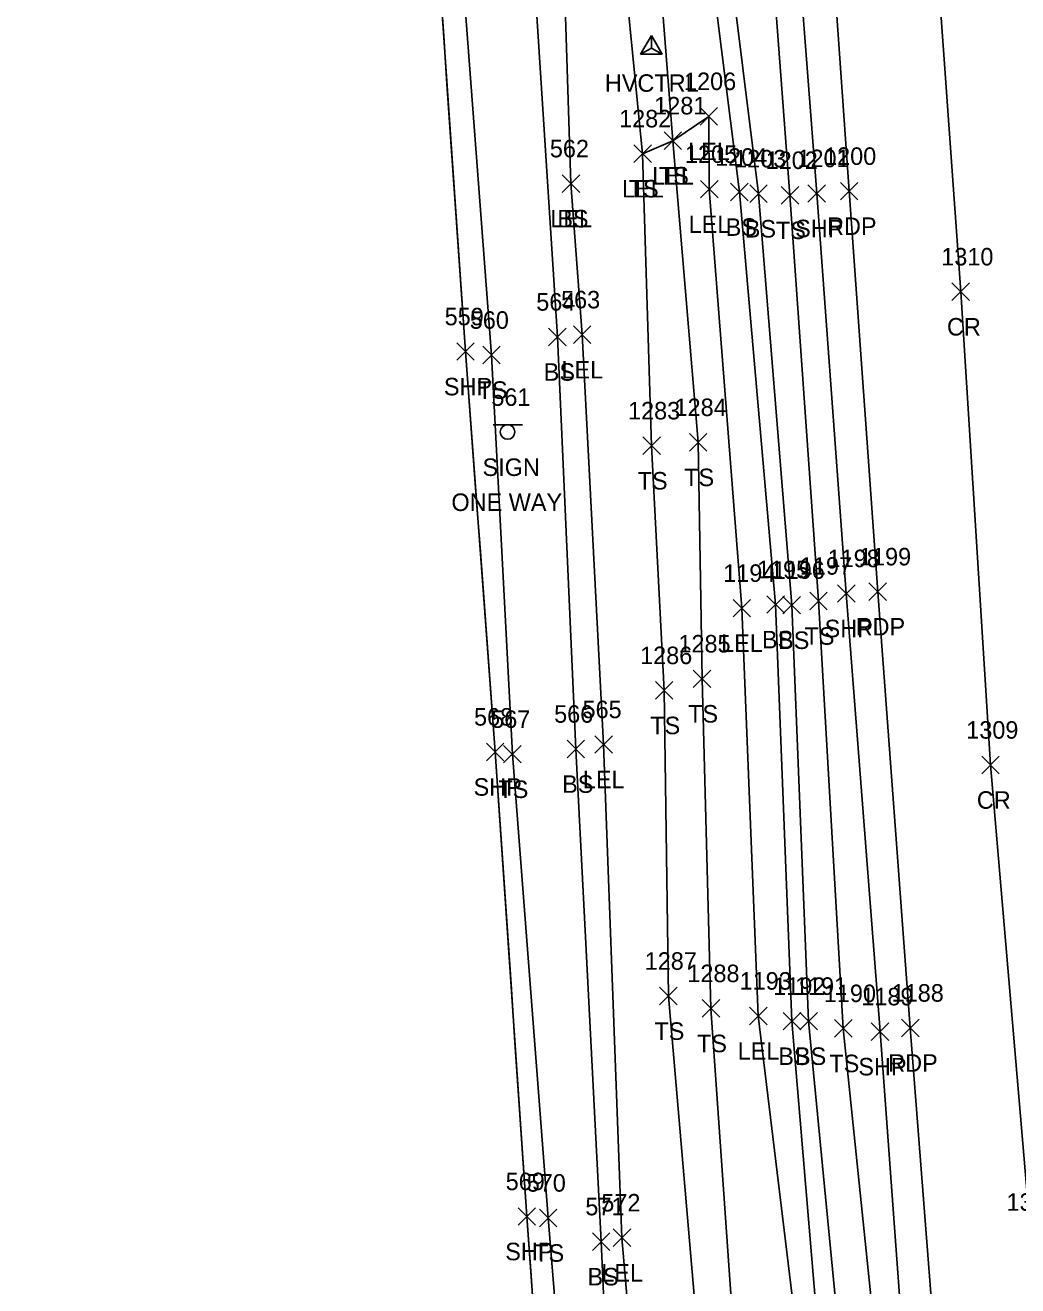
# Model space of a CAD drawing. Extents: x 1650221 to 1650634, y 244606 to 249996.
# Drawn here: x 1650231.8 to 1650345.1, y 246477.6 to 246621.5 of the extents above; entities that cross this region are included whole.
import ezdxf

# ---------------------------------------------------------------- set-up
doc = ezdxf.new("R2010")
doc.units = 0
for name, color, linetype in [('C_A', 7, 'Continuous'), ('CPSM', 7, 'Continuous'), ('L_A', 7, 'Continuous'), ('L_I', 7, 'Continuous'), ('L_TIC', 7, 'Continuous'), ('LARO', 7, 'Continuous'), ('LELB', 7, 'Continuous'), ('LSOGP', 7, 'Continuous'), ('P_A', 7, 'Continuous'), ('P_I', 7, 'Continuous'), ('P_TIC', 7, 'Continuous'), ('PET', 7, 'Continuous'), ('PRC', 7, 'Continuous'), ('PSP', 7, 'Continuous'), ('S_A', 7, 'Continuous'), ('S_C', 7, 'Continuous'), ('S_I', 7, 'Continuous'), ('SSGN', 7, 'Continuous')]:
    doc.layers.add(name, color=color, linetype=linetype)

msp = doc.modelspace()

# ---------------------------------------------------------------- linework, layer by layer
at = {"layer": 'CPSM'}
for p, q in [((1650302.02, 246618.14), (1650303.27, 246620.3)), ((1650304.52, 246618.14), (1650303.27, 246620.3)), ((1650303.27, 246618.86), (1650303.27, 246620.3)), ((1650302.02, 246618.14), (1650303.27, 246618.86)), ((1650302.02, 246618.14), (1650304.52, 246618.14)), ((1650303.27, 246618.86), (1650303.27, 246618.86)), ((1650303.27, 246618.86), (1650304.52, 246618.14))]:
    msp.add_line(p, q, dxfattribs=at)
at = {"layer": 'L_TIC'}
for points in [[(1650308.83, 246610.06), (1650310.83, 246612.06)], [(1650310.83, 246610.06), (1650308.83, 246612.06)], [(1650304.72, 246607.28), (1650306.72, 246609.28)], [(1650306.72, 246607.28), (1650304.72, 246609.28)], [(1650304.72, 246607.28), (1650306.72, 246609.28)], [(1650306.72, 246607.28), (1650304.72, 246609.28)], [(1650301.28, 246605.8), (1650303.28, 246607.8)], [(1650303.28, 246605.8), (1650301.28, 246607.8)], [(1650301.28, 246605.8), (1650303.28, 246607.8)], [(1650303.28, 246605.8), (1650301.28, 246607.8)], [(1650293.1, 246602.38), (1650295.1, 246604.38)], [(1650295.1, 246602.38), (1650293.1, 246604.38)], [(1650293.1, 246602.38), (1650295.1, 246604.38)], [(1650295.1, 246602.38), (1650293.1, 246604.38)], [(1650308.88, 246601.74), (1650310.88, 246603.74)], [(1650310.88, 246601.74), (1650308.88, 246603.74)], [(1650312.31, 246601.42), (1650314.31, 246603.42)], [(1650314.31, 246601.42), (1650312.31, 246603.42)], [(1650314.49, 246601.23), (1650316.49, 246603.23)], [(1650316.49, 246601.23), (1650314.49, 246603.23)], [(1650318.08, 246601.05), (1650320.08, 246603.05)], [(1650320.08, 246601.05), (1650318.08, 246603.05)], [(1650291.55, 246584.88), (1650293.55, 246586.88)], [(1650293.55, 246584.88), (1650291.55, 246586.88)], [(1650294.38, 246585.14), (1650296.38, 246587.14)], [(1650296.38, 246585.14), (1650294.38, 246587.14)], [(1650284.04, 246582.81), (1650286.04, 246584.81)], [(1650286.04, 246582.81), (1650284.04, 246584.81)], [(1650302.3, 246572.46), (1650304.3, 246574.46)], [(1650304.3, 246572.46), (1650302.3, 246574.46)], [(1650307.61, 246572.85), (1650309.61, 246574.85)], [(1650309.61, 246572.85), (1650307.61, 246574.85)], [(1650316.45, 246554.33), (1650318.45, 246556.33)], [(1650318.45, 246554.33), (1650316.45, 246556.33)], [(1650318.29, 246554.26), (1650320.29, 246556.26)], [(1650320.29, 246554.26), (1650318.29, 246556.26)], [(1650321.34, 246554.74), (1650323.34, 246556.74)], [(1650323.34, 246554.74), (1650321.34, 246556.74)], [(1650312.59, 246553.92), (1650314.59, 246555.92)], [(1650314.59, 246553.92), (1650312.59, 246555.92)], [(1650308.06, 246545.86), (1650310.06, 246547.86)], [(1650310.06, 246545.86), (1650308.06, 246547.86)], [(1650303.74, 246544.53), (1650305.74, 246546.53)], [(1650305.74, 246544.53), (1650303.74, 246546.53)], [(1650286.41, 246537.25), (1650288.41, 246539.25)], [(1650288.41, 246537.25), (1650286.41, 246539.25)], [(1650293.65, 246537.84), (1650295.65, 246539.84)], [(1650295.65, 246537.84), (1650293.65, 246539.84)], [(1650296.83, 246538.36), (1650298.83, 246540.36)], [(1650298.83, 246538.36), (1650296.83, 246540.36)], [(1650304.21, 246509.64), (1650306.21, 246511.64)], [(1650306.21, 246509.64), (1650304.21, 246511.64)], [(1650309.07, 246508.23), (1650311.07, 246510.23)], [(1650311.07, 246508.23), (1650309.07, 246510.23)], [(1650314.47, 246507.37), (1650316.47, 246509.37)], [(1650316.47, 246507.37), (1650314.47, 246509.37)], [(1650320.21, 246506.78), (1650322.21, 246508.78)], [(1650322.21, 246506.78), (1650320.21, 246508.78)], [(1650318.31, 246506.77), (1650320.31, 246508.77)], [(1650320.31, 246506.77), (1650318.31, 246508.77)], [(1650324.17, 246505.95), (1650326.17, 246507.95)], [(1650326.17, 246505.95), (1650324.17, 246507.95)], [(1650290.5, 246484.31), (1650292.5, 246486.31)], [(1650292.5, 246484.31), (1650290.5, 246486.31)], [(1650296.54, 246481.61), (1650298.54, 246483.61)], [(1650298.54, 246481.61), (1650296.54, 246483.61)], [(1650298.92, 246482.05), (1650300.92, 246484.05)], [(1650300.92, 246482.05), (1650298.92, 246484.05)]]:
    msp.add_lwpolyline(points, dxfattribs=at)
at = {"layer": 'LARO'}
for points in [[(1650320.4, 246329.58), (1650323.59, 246329.49), (1650329.36, 246338.84), (1650329.27, 246368.96), (1650324.06, 246419.57), (1650321.53, 246458.18), (1650315.47, 246508.37), (1650313.59, 246554.92), (1650309.88, 246602.74), (1650309.83, 246611.06), (1650305.72, 246608.28), (1650302.28, 246606.8)], [(1650294.1, 246603.38), (1650295.38, 246586.14), (1650297.83, 246539.36), (1650299.92, 246483.05), (1650303.91, 246436.92), (1650306.04, 246379), (1650309.27, 246340.34)]]:
    msp.add_lwpolyline(points, dxfattribs=at)
at = {"layer": 'LELB'}
for points in [[(1650242.27, 247235.36), (1650241.91, 247206.66), (1650243.27, 247168.76), (1650246.51, 247128.17), (1650248.83, 247083.97), (1650252.85, 247030.65), (1650256.86, 246977.49), (1650260.95, 246918.52), (1650265.57, 246863.83), (1650269.89, 246812.16), (1650273.23, 246757.17), (1650276.03, 246723.56), (1650279.21, 246672.89), (1650281.34, 246632.54), (1650285.04, 246583.81), (1650287.41, 246538.25), (1650291.5, 246485.31), (1650295.53, 246435.79), (1650299.48, 246380.33), (1650302.27, 246339.43), (1650306.13, 246294.16), (1650309.79, 246242.03)], [(1650254.94, 247226.35), (1650251.19, 247207.91), (1650256.12, 247169.21), (1650259.77, 247133.43), (1650260.76, 247116.75), (1650264.32, 247083.63), (1650267.53, 247032.12), (1650271.47, 246976.78), (1650276.33, 246918.79), (1650279.06, 246862.8), (1650283.73, 246813.9), (1650289.01, 246756.82), (1650289.41, 246725.67), (1650289.28, 246672.86), (1650289.57, 246632.6), (1650292.55, 246585.88), (1650294.65, 246538.84), (1650297.54, 246482.61), (1650299.6, 246436.73), (1650304.05, 246378.94), (1650306.26, 246339.81), (1650313.05, 246293.73), (1650316.43, 246243)], [(1650334.26, 246221.72), (1650338.38, 246258.83), (1650337.59, 246300.3), (1650334.07, 246349), (1650333.58, 246369.4), (1650328.81, 246417.14), (1650325.98, 246458.24), (1650321.21, 246507.78), (1650319.29, 246555.26), (1650315.49, 246602.23), (1650308.36, 246659.65), (1650298.25, 246716.86), (1650297.89, 246733.14), (1650297.15, 246741.44), (1650293.34, 246760.07), (1650289.93, 246790.87)], [(1650347.02, 246221.82), (1650344.37, 246259.89), (1650340.76, 246300.88), (1650337.02, 246349.32), (1650337.24, 246369.2), (1650333.16, 246417.65), (1650330.19, 246458.39), (1650325.17, 246506.95), (1650322.34, 246555.74), (1650319.08, 246602.05), (1650314.68, 246660.27), (1650309.78, 246717), (1650303.8, 246759.84), (1650302.49, 246790.4)], [(1650297.97, 246685.4), (1650291.99, 246672.81), (1650293.12, 246633.23), (1650294.1, 246603.38)], [(1650330.33, 246258.11), (1650336.61, 246267.66), (1650335.63, 246300.25), (1650332.47, 246348.54), (1650331.57, 246369.5), (1650326.35, 246417.18), (1650323.43, 246458.49), (1650319.31, 246507.77), (1650317.45, 246555.33), (1650313.31, 246602.42), (1650309.77, 246630.78), (1650304.43, 246659.77), (1650299.11, 246683.43)], [(1650298.24, 246680.39), (1650300.27, 246657.56), (1650304.04, 246629.74), (1650305.72, 246608.28), (1650308.61, 246573.85), (1650309.06, 246546.86), (1650310.07, 246509.23), (1650312.74, 246470.67), (1650317.63, 246430.23), (1650317.82, 246407.13), (1650317.23, 246391.9), (1650323.59, 246373.12), (1650321.28, 246359.92), (1650319.29, 246343.11), (1650319.42, 246332.82)], [(1650298.24, 246680.39), (1650298.51, 246657.16), (1650299.98, 246629.97), (1650302.28, 246606.8), (1650303.3, 246573.46), (1650304.74, 246545.53), (1650305.21, 246510.64), (1650309.03, 246466.31), (1650311.77, 246430.96), (1650313.2, 246406.98), (1650311.23, 246390.61), (1650317.47, 246372.39), (1650313.3, 246358.43), (1650314.37, 246342.06), (1650319.42, 246332.82)]]:
    msp.add_lwpolyline(points, dxfattribs=at)
at = {"layer": 'LSOGP'}
msp.add_lwpolyline([(1650279.17, 246626.2), (1650279.58, 246620.2), (1650279.99, 246614.2), (1650280.41, 246608.2), (1650280.82, 246602.21), (1650281.24, 246596.21), (1650281.65, 246590.21), (1650282.06, 246584.21), (1650282.49, 246578.5), (1650282.91, 246572.79), (1650283.33, 246567.08), (1650283.76, 246561.36), (1650284.18, 246555.65), (1650284.61, 246549.94), (1650285.03, 246544.23), (1650285.45, 246538.51), (1650285.9, 246531.89), (1650286.36, 246525.26), (1650286.81, 246518.63), (1650287.26, 246512), (1650287.71, 246505.37), (1650288.16, 246498.74), (1650288.61, 246492.11), (1650289.06, 246485.48), (1650289.51, 246479.26), (1650289.95, 246473.04)], dxfattribs=at)
at = {"layer": 'P_TIC'}
for points in [[(1650321.14, 246601.26), (1650323.14, 246603.26)], [(1650323.14, 246601.26), (1650321.14, 246603.26)], [(1650324.84, 246601.52), (1650326.84, 246603.52)], [(1650326.84, 246601.52), (1650324.84, 246603.52)], [(1650337.57, 246590.04), (1650339.57, 246592.04)], [(1650339.57, 246590.04), (1650337.57, 246592.04)], [(1650281.06, 246583.21), (1650283.06, 246585.21)], [(1650283.06, 246583.21), (1650281.06, 246585.21)], [(1650328.1, 246555.8), (1650330.1, 246557.8)], [(1650330.1, 246555.8), (1650328.1, 246557.8)], [(1650324.51, 246555.6), (1650326.51, 246557.6)], [(1650326.51, 246555.6), (1650324.51, 246557.6)], [(1650284.45, 246537.51), (1650286.45, 246539.51)], [(1650286.45, 246537.51), (1650284.45, 246539.51)], [(1650340.97, 246536.02), (1650342.97, 246538.02)], [(1650342.97, 246536.02), (1650340.97, 246538.02)], [(1650328.36, 246505.58), (1650330.36, 246507.58)], [(1650330.36, 246505.58), (1650328.36, 246507.58)], [(1650331.81, 246506), (1650333.81, 246508)], [(1650333.81, 246506), (1650331.81, 246508)], [(1650288.06, 246484.48), (1650290.06, 246486.48)], [(1650290.06, 246484.48), (1650288.06, 246486.48)]]:
    msp.add_lwpolyline(points, dxfattribs=at)
at = {"layer": 'PET'}
msp.add_lwpolyline([(1650353.63, 246221.52), (1650350.67, 246260.72), (1650347.78, 246301.59), (1650344.6, 246348.96), (1650342.99, 246369.43), (1650339.44, 246417.63), (1650336.53, 246459.1), (1650332.81, 246507), (1650329.1, 246556.8), (1650325.84, 246602.52), (1650321.75, 246661.01), (1650317.87, 246717.27), (1650314.55, 246761.47), (1650311.27, 246802.48), (1650308.51, 246843.59), (1650304.95, 246897.23), (1650300.96, 246950.35), (1650297.4, 247001.83), (1650293.63, 247056.22), (1650290.13, 247106.77), (1650285.97, 247166.23), (1650282.75, 247212.34), (1650279.98, 247248.95)], dxfattribs=at)
at = {"layer": 'PRC'}
msp.add_lwpolyline([(1650365.1, 246222.23), (1650362.04, 246265.67), (1650358.21, 246317.53), (1650354.88, 246368.98), (1650350.4, 246428.86), (1650346.57, 246483.13), (1650341.97, 246537.02), (1650338.57, 246591.04), (1650334.55, 246647.32), (1650330.72, 246698.07), (1650326.82, 246753.45), (1650322.93, 246808.73), (1650318.78, 246866.3), (1650315.63, 246915.25), (1650311.69, 246971.18), (1650308.09, 247021.19), (1650305.21, 247068.94), (1650301.6, 247120.36), (1650298.8, 247160.8), (1650294.82, 247207.2), (1650291.45, 247257.79)], dxfattribs=at)
at = {"layer": 'PSP'}
for points in [[(1650231.83, 247264.44), (1650236.38, 247206.75), (1650239.4, 247169.19), (1650242.51, 247127.54), (1650245.5, 247084.02), (1650249.81, 247030.22), (1650253.62, 246978.01), (1650257.98, 246918.58), (1650261.69, 246863.47), (1650265.43, 246811.71), (1650269.36, 246757.46), (1650271.77, 246723.3), (1650275.43, 246673.04), (1650278.75, 246632.2), (1650282.06, 246584.21), (1650285.45, 246538.51), (1650289.06, 246485.48), (1650292.63, 246435.74), (1650296.7, 246380.37), (1650299.48, 246339.42), (1650302.95, 246294.11), (1650306.82, 246242.11)], [(1650349.68, 246222.04), (1650346.67, 246260.34), (1650343.46, 246301.15), (1650340.56, 246349.22), (1650338.99, 246369.3), (1650335.68, 246417.66), (1650332.87, 246458.75), (1650329.36, 246506.58), (1650325.51, 246556.6), (1650322.14, 246602.26), (1650317.67, 246660.67), (1650313.65, 246716.62), (1650310.76, 246760.87), (1650307.66, 246803.03), (1650304.71, 246843.75), (1650300.95, 246897.67), (1650297.16, 246949.75), (1650293.72, 247001.93), (1650289.97, 247055.55), (1650286.03, 247107.65), (1650281.83, 247165.68), (1650278.51, 247212.85), (1650276.66, 247249.86)]]:
    msp.add_lwpolyline(points, dxfattribs=at)
at = {"layer": 'SSGN'}
for p, q in [((1650285.22, 246575.86), (1650288.56, 246575.86)), ((1650286.87, 246575.03), (1650286.87, 246575.03))]:
    msp.add_line(p, q, dxfattribs=at)
msp.add_circle((1650286.87, 246575.03), 0.833, dxfattribs=at)

# ---------------------------------------------------------------- texts
at = {"layer": 'C_A'}
msp.add_text('HVCTRL', height=2, dxfattribs=at).set_placement((1650297.97, 246613.86))
at = {"layer": 'L_A'}
for s, p in [('LEL', (1650307.46, 246606.06)), ('LEL', (1650303.36, 246603.28)), ('TS', (1650304.13, 246603.28)), ('LEL', (1650299.92, 246601.8)), ('TS', (1650300.69, 246601.8)), ('LEL', (1650291.74, 246598.38)), ('BS', (1650292.54, 246598.38)), ('LEL', (1650307.52, 246597.74)), ('BS', (1650311.75, 246597.42)), ('BS', (1650313.93, 246597.23)), ('TS', (1650317.49, 246597.05)), ('BS', (1650290.99, 246580.88)), ('LEL', (1650293.01, 246581.14)), ('TS', (1650283.45, 246578.81)), ('TS', (1650307.02, 246568.85)), ('TS', (1650301.71, 246568.46)), ('BS', (1650315.89, 246550.33)), ('BS', (1650317.73, 246550.26)), ('TS', (1650320.75, 246550.74)), ('LEL', (1650311.23, 246549.92)), ('TS', (1650307.47, 246541.86)), ('TS', (1650303.15, 246540.53)), ('LEL', (1650295.46, 246534.36)), ('TS', (1650285.82, 246533.25)), ('BS', (1650293.09, 246533.84)), ('TS', (1650303.62, 246505.64)), ('TS', (1650308.48, 246504.23)), ('LEL', (1650313.11, 246503.37)), ('BS', (1650317.75, 246502.77)), ('BS', (1650319.66, 246502.78)), ('TS', (1650323.58, 246501.95)), ('TS', (1650289.91, 246480.31)), ('LEL', (1650297.56, 246478.05)), ('BS', (1650295.98, 246477.61))]:
    msp.add_text(s, height=2, dxfattribs=at).set_placement(p)
at = {"layer": 'L_I'}
for s, p in [('1206', (1650307, 246614.06)), ('1281', (1650303.6, 246611.28)), ('1281', (1650303.6, 246611.28)), ('1282', (1650299.59, 246609.8)), ('1282', (1650299.59, 246609.8)), ('562', (1650291.69, 246606.38)), ('562', (1650291.69, 246606.38)), ('1205', (1650307.11, 246605.74)), ('1204', (1650310.54, 246605.42)), ('1203', (1650312.72, 246605.23)), ('1202', (1650316.31, 246605.05)), ('564', (1650290.14, 246588.88)), ('563', (1650292.97, 246589.14)), ('560', (1650282.55, 246586.81)), ('1283', (1650300.61, 246576.46)), ('1284', (1650305.92, 246576.85)), ('1197', (1650320.22, 246558.74)), ('1194', (1650311.47, 246557.92)), ('1195', (1650315.32, 246558.33)), ('1196', (1650317.11, 246558.26)), ('1286', (1650301.99, 246548.53)), ('1285', (1650306.36, 246549.86)), ('566', (1650292.18, 246541.84)), ('565', (1650295.42, 246542.36)), ('567', (1650285, 246541.25)), ('1287', (1650302.51, 246513.64)), ('1288', (1650307.38, 246512.23)), ('1193', (1650313.34, 246511.37)), ('1192', (1650317.18, 246510.77)), ('1191', (1650319.66, 246510.78)), ('1190', (1650322.95, 246509.95)), ('570', (1650289.05, 246488.31)), ('571', (1650295.74, 246485.61)), ('572', (1650297.56, 246486.05))]:
    msp.add_text(s, height=2, dxfattribs=at).set_placement(p)
at = {"layer": 'P_A'}
for s, p in [('RDP', (1650323.32, 246597.52)), ('SHP', (1650319.68, 246597.26)), ('CR', (1650337, 246586.04)), ('SHP', (1650279.6, 246579.21)), ('SHP', (1650323.04, 246551.6)), ('RDP', (1650326.58, 246551.8)), ('SHP', (1650282.99, 246533.51)), ('CR', (1650340.41, 246532.02)), ('SHP', (1650326.89, 246501.58)), ('RDP', (1650330.3, 246502)), ('SHP', (1650286.6, 246480.48))]:
    msp.add_text(s, height=2, dxfattribs=at).set_placement(p)
at = {"layer": 'P_I'}
for s, p in [('1201', (1650319.94, 246605.26)), ('1200', (1650322.98, 246605.52)), ('1310', (1650336.35, 246594.04)), ('559', (1650279.69, 246587.21)), ('1198', (1650323.38, 246559.6)), ('1199', (1650326.96, 246559.8)), ('568', (1650283.04, 246541.51)), ('1309', (1650339.2, 246540.02)), ('1188', (1650330.69, 246510)), ('1189', (1650327.23, 246509.58)), ('569', (1650286.65, 246488.48)), ('1308', (1650343.8, 246486.13))]:
    msp.add_text(s, height=2, dxfattribs=at).set_placement(p)
at = {"layer": 'S_A'}
msp.add_text('SIGN', height=2, dxfattribs=at).set_placement((1650284.01, 246570.01))
at = {"layer": 'S_C'}
msp.add_text('ONE WAY', height=2, dxfattribs=at).set_placement((1650280.46, 246566.01))
at = {"layer": 'S_I'}
msp.add_text('561', height=2, dxfattribs=at).set_placement((1650285.01, 246578.01))

doc.saveas('drawing.dxf')
